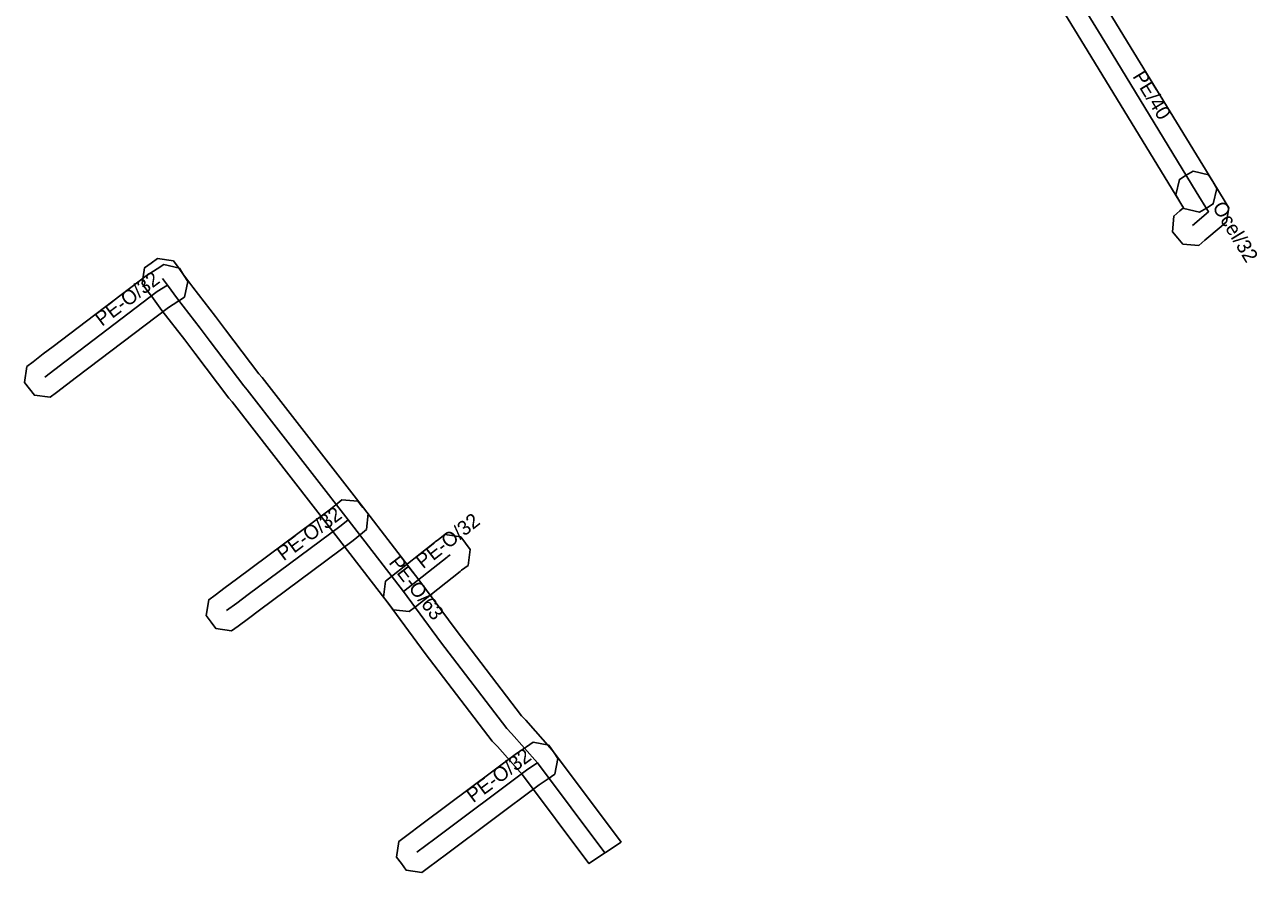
# Model space of a CAD drawing. Extents: x -492768 to -492424, y -1126490 to -1126252.
# Drawn here: x -492637.4 to -492573.5, y -1126420.6 to -1126376.7 of the extents above; entities that cross this region are included whole.
import ezdxf

# ---------------------------------------------------------------- set-up
doc = ezdxf.new("R2010")
doc.units = 0
for name, color, linetype in [('1', 7, 'Continuous'), ('24', 7, 'Continuous'), ('30', 7, 'Continuous')]:
    doc.layers.add(name, color=color, linetype=linetype)

msp = doc.modelspace()

# ---------------------------------------------------------------- linework, layer by layer
at = {"layer": '1'}
for points in [[(-492577.298, -1126386.19), (-492577.514, -1126385.836), (-492582.119, -1126378.292), (-492584.142, -1126374.977), (-492584.551, -1126374.563), (-492584.842, -1126374.268), (-492584.838, -1126373.44), (-492584.543, -1126373.149), (-492584.248, -1126372.858), (-492583.42, -1126372.862), (-492583.129, -1126373.157), (-492582.556, -1126373.737), (-492580.411, -1126377.25), (-492575.806, -1126384.794), (-492575.59, -1126385.148), (-492575.785, -1126385.953), (-492576.139, -1126386.169), (-492576.493, -1126386.385)], [(-492576.022, -1126384.441), (-492575.806, -1126384.794), (-492575.171, -1126385.835), (-492574.979, -1126386.15), (-492575.096, -1126386.877), (-492575.376, -1126387.116), (-492576.212, -1126387.83), (-492576.527, -1126388.099), (-492577.352, -1126388.034), (-492577.621, -1126387.719), (-492577.89, -1126387.404), (-492577.825, -1126386.579), (-492577.51, -1126386.31), (-492577.323, -1126386.149), (-492577.514, -1126385.836), (-492577.729, -1126385.482), (-492577.534, -1126384.677), (-492577.181, -1126384.461), (-492576.827, -1126384.246)], [(-492606.468, -1126419.011), (-492608.135, -1126420.122), (-492611.576, -1126415.532), (-492612.876, -1126414.057), (-492613.14, -1126413.782), (-492616.62, -1126409.24), (-492618.539, -1126406.632), (-492621.4, -1126402.923), (-492626.626, -1126396.211), (-492626.8, -1126396.006), (-492628.558, -1126393.683), (-492629.074, -1126392.998), (-492630.258, -1126391.472), (-492630.786, -1126390.752), (-492631.036, -1126390.412), (-492631.281, -1126390.079), (-492631.156, -1126389.26), (-492630.822, -1126389.014), (-492630.489, -1126388.769), (-492629.67, -1126388.894), (-492629.424, -1126389.228), (-492629.174, -1126389.568), (-492628.662, -1126390.268), (-492627.486, -1126391.782), (-492626.962, -1126392.477), (-492625.24, -1126394.754), (-492625.074, -1126394.949), (-492619.82, -1126401.697), (-492616.941, -1126405.428), (-492615.02, -1126408.04), (-492611.62, -1126412.478), (-492611.404, -1126412.703), (-492610.024, -1126414.268)], [(-492629.094, -1126390.782), (-492629.444, -1126391.004), (-492629.929, -1126391.312), (-492634.687, -1126394.928), (-492635.205, -1126395.316), (-492635.72, -1126395.713), (-492636.048, -1126395.965), (-492636.87, -1126395.858), (-492637.123, -1126395.53), (-492637.375, -1126395.202), (-492637.268, -1126394.38), (-492636.94, -1126394.127), (-492636.415, -1126393.724), (-492635.893, -1126393.332), (-492631.071, -1126389.668), (-492630.516, -1126389.316), (-492630.166, -1126389.094), (-492629.358, -1126389.274), (-492629.136, -1126389.624), (-492628.914, -1126389.974)], [(-492619.652, -1126402.813), (-492619.97, -1126403.078), (-492620.352, -1126403.396), (-492625.2, -1126406.99), (-492625.781, -1126407.431), (-492626.317, -1126407.825), (-492626.651, -1126408.071), (-492627.47, -1126407.946), (-492627.715, -1126407.613), (-492627.961, -1126407.279), (-492627.836, -1126406.46), (-492627.503, -1126406.215), (-492626.979, -1126405.829), (-492626.4, -1126405.39), (-492621.588, -1126401.824), (-492621.25, -1126401.542), (-492620.932, -1126401.277), (-492620.107, -1126401.352), (-492619.842, -1126401.67), (-492619.577, -1126401.988)], [(-492618.359, -1126405.244), (-492616.141, -1126403.497), (-492616.107, -1126403.463), (-492615.93, -1126403.33), (-492615.599, -1126403.081), (-492614.779, -1126403.199), (-492614.53, -1126403.53), (-492614.281, -1126403.861), (-492614.399, -1126404.681), (-492614.73, -1126404.93), (-492614.794, -1126404.978), (-492614.815, -1126404.999), (-492617.121, -1126406.816), (-492617.447, -1126407.072), (-492618.27, -1126406.974), (-492618.526, -1126406.649), (-492618.782, -1126406.323), (-492618.684, -1126405.5)], [(-492609.895, -1126415.494), (-492610.238, -1126415.727), (-492610.719, -1126416.054), (-492615.523, -1126419.642), (-492616.454, -1126420.333), (-492616.787, -1126420.58), (-492617.606, -1126420.459), (-492617.853, -1126420.126), (-492618.1, -1126419.793), (-492617.979, -1126418.974), (-492617.646, -1126418.727), (-492616.717, -1126418.038), (-492611.881, -1126414.426), (-492611.362, -1126414.073), (-492611.019, -1126413.84), (-492610.206, -1126413.995), (-492609.973, -1126414.338), (-492609.74, -1126414.681)]]:
    msp.add_lwpolyline(points, close=True, dxfattribs=at)
at = {"layer": '24'}
for points in [[(-492576.66, -1126385.315), (-492581.265, -1126377.771), (-492583.349, -1126374.357), (-492583.84, -1126373.86)], [(-492576.66, -1126385.315), (-492576.025, -1126386.356), (-492576.861, -1126387.07)], [(-492629.98, -1126390.16), (-492630.5, -1126390.49), (-492635.29, -1126394.13), (-492635.81, -1126394.52), (-492636.33, -1126394.92)], [(-492630.23, -1126389.82), (-492629.98, -1126390.16), (-492629.46, -1126390.87), (-492628.28, -1126392.39), (-492627.76, -1126393.08), (-492626.02, -1126395.38), (-492625.85, -1126395.58), (-492620.61, -1126402.31), (-492617.74, -1126406.03), (-492615.82, -1126408.64), (-492612.38, -1126413.13), (-492612.14, -1126413.38), (-492610.8, -1126414.9), (-492607.302, -1126419.567)], [(-492620.61, -1126402.31), (-492620.97, -1126402.61), (-492625.8, -1126406.19), (-492626.38, -1126406.63), (-492626.91, -1126407.02)], [(-492617.74, -1126406.03), (-492615.48, -1126404.25), (-492615.45, -1126404.22), (-492615.33, -1126404.13)], [(-492610.8, -1126414.9), (-492611.3, -1126415.24), (-492616.12, -1126418.84), (-492617.05, -1126419.53)]]:
    msp.add_lwpolyline(points, dxfattribs=at)

# ---------------------------------------------------------------- texts
at = {"layer": '30'}
for s, rotation, p in [('PE/40', 301.40068, (-492579.986, -1126379.338)), ('Ocel/32', 301.38279, (-492575.856, -1126386.105)), ('PE-O/32', 37.2318, (-492633.37, -1126392.319)), ('PE-O/32', 36.54587, (-492623.954, -1126404.473)), ('PE-O/32', 38.22434, (-492616.734, -1126404.88)), ('PE-O/63', 307.65038, (-492618.537, -1126404.538)), ('PE-O/32', 36.75561, (-492614.132, -1126417.006))]:
    msp.add_text(s, height=0.75, rotation=rotation, dxfattribs=at).set_placement(p)

doc.saveas('drawing.dxf')
